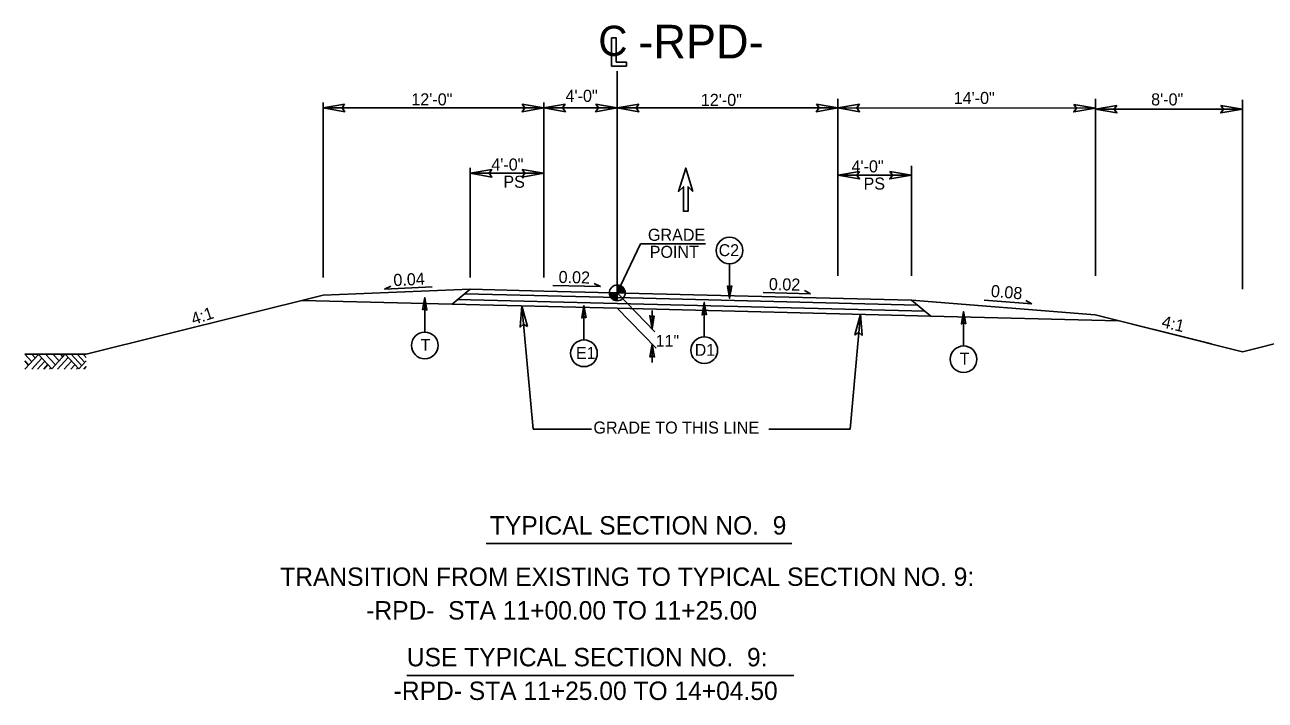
# Model space of a CAD drawing. Extents: x 1901582 to 1902252, y 193723 to 194156.
# Drawn here: x 1902017 to 1902084.4, y 193732 to 193768.8 of the extents above; entities that cross this region are included whole.
import ezdxf

# ---------------------------------------------------------------- set-up
doc = ezdxf.new("R2010")
doc.units = 0
for name, color, linetype in [('Old_Level_1', 7, 'Continuous'), ('Old_Level_11', 7, 'Continuous'), ('Old_Level_2', 7, 'Continuous'), ('Old_Level_20', 7, 'Continuous'), ('Prop Dimension', 7, 'Continuous'), ('Prop Dimension Text', 7, 'Continuous'), ('Typical Grade Point Symbol CELL', 7, 'Continuous'), ('Typical Pavement Slope Information CELL', 7, 'Continuous'), ('Typical Slope Point Local CELL', 7, 'Continuous'), ('Typical Terminator CELL', 7, 'Continuous'), ('Typical Text Centerline CELL', 7, 'Continuous'), ('Typical Text General CELL', 7, 'Continuous'), ('Typical Text Grade Point CELL', 7, 'Continuous')]:
    doc.layers.add(name, color=color, linetype=linetype)

# ---------------------------------------------------------------- blocks, each defined once
blk = doc.blocks.new('TERMINATOR')
at = {"layer": 'Typical Terminator CELL'}
blk.add_lwpolyline([(-0.469, 0.081), (0, 0), (-0.471, -0.083), (-0.411, 0)], close=True, dxfattribs=at)

msp = doc.modelspace()

# ---------------------------------------------------------------- linework, layer by layer
at = {"layer": 'Old_Level_1'}
for p, q in [((1902083.192, 193754.369), (1902083.192, 193764.667)), ((1902075.193, 193764.167), (1902083.193, 193764.167)), ((1902041.192, 193754.359), (1902033.192, 193754.039)), ((1902041.196, 193754.359), (1902040.203, 193753.551)), ((1902040.899, 193754.117), (1902049.192, 193753.909)), ((1902041.192, 193754.359), (1902045.193, 193754.259)), ((1902045.193, 193754.259), (1902065.192, 193753.759)), ((1902049.192, 193754.159), (1902051.241, 193752.043)), ((1902033.192, 193754.039), (1902020.31, 193750.819)), ((1902032.052, 193753.754), (1902040.203, 193753.551)), ((1902040.203, 193753.551), (1902049.192, 193753.326)), ((1902040.501, 193753.793), (1902049.192, 193753.576)), ((1902044.001, 193753.456), (1902044.618, 193746.746)), ((1902049.192, 193753.909), (1902065.511, 193753.501)), ((1902049.192, 193753.576), (1902065.933, 193753.157)), ((1902065.194, 193753.759), (1902075.192, 193752.959)), ((1902065.194, 193753.759), (1902066.25, 193752.899)), ((1902049.192, 193753.326), (1902066.25, 193752.899)), ((1902049.192, 193753.326), (1902051.299, 193751.15)), ((1902051.084, 193753.206), (1902051.084, 193752.206)), ((1902062.424, 193752.995), (1902061.85, 193746.746)), ((1902066.25, 193752.899), (1902076.453, 193752.644)), ((1902075.192, 193752.959), (1902081.514, 193751.379)), ((1902051.084, 193751.372), (1902051.084, 193750.372)), ((1902047.786, 193746.746), (1902044.618, 193746.746)), ((1902061.85, 193746.746), (1902057.427, 193746.746))]:
    msp.add_line(p, q, dxfattribs=at)
for points in [[(1902075.192, 193752.959), (1902083.192, 193750.959)], [(1902091.192, 193752.959), (1902083.192, 193750.959)], [(1902016.968, 193750.819), (1902020.31, 193750.819)]]:
    msp.add_lwpolyline(points, dxfattribs=at)
at = {"layer": 'Old_Level_11'}
for p, q in [((1902049.192, 193754.159), (1902049.193, 193766.232)), ((1902055.296, 193755.742), (1902055.296, 193753.868)), ((1902038.722, 193752.027), (1902038.722, 193753.902)), ((1902047.381, 193751.598), (1902047.381, 193753.473)), ((1902053.924, 193751.764), (1902053.924, 193753.638)), ((1902068.027, 193751.273), (1902068.027, 193753.147)), ((1902016.968, 193750.819), (1902017.343, 193750.416)), ((1902016.968, 193750.014), (1902017.71, 193750.811)), ((1902017.343, 193750.819), (1902017.53, 193750.618)), ((1902017.71, 193750.811), (1902018.434, 193750.032)), ((1902018.101, 193750.819), (1902018.634, 193750.246)), ((1902018.434, 193750.032), (1902019.165, 193750.818)), ((1902018.499, 193750.819), (1902018.832, 193750.46)), ((1902018.901, 193750.819), (1902019.034, 193750.676)), ((1902019.165, 193750.818), (1902019.906, 193750.022)), ((1902019.487, 193750.819), (1902020.067, 193750.196)), ((1902019.82, 193750.819), (1902020.234, 193750.375)), ((1902020.14, 193750.819), (1902020.31, 193750.636)), ((1902016.968, 193750.457), (1902017.174, 193750.235)), ((1902017.342, 193750.014), (1902017.896, 193750.61)), ((1902017.651, 193750.014), (1902018.052, 193750.443)), ((1902017.998, 193750.014), (1902018.225, 193750.257)), ((1902018.309, 193750.014), (1902018.38, 193750.09)), ((1902018.744, 193750.014), (1902019.33, 193750.642)), ((1902019.114, 193750.014), (1902019.514, 193750.443)), ((1902019.48, 193750.014), (1902019.697, 193750.247)), ((1902019.775, 193750.014), (1902019.844, 193750.088)), ((1902019.906, 193750.022), (1902020.31, 193750.457)), ((1902020.176, 193750.014), (1902020.31, 193750.157)), ((1902042.053, 193740.514), (1902058.679, 193740.514)), ((1902037.745, 193733.341), (1902058.8, 193733.341))]:
    msp.add_line(p, q, dxfattribs=at)
for points in [[(1902055.181, 193754.54), (1902055.296, 193753.868), (1902055.416, 193754.543), (1902055.296, 193754.458)], [(1902038.606, 193753.23), (1902038.722, 193753.902), (1902038.841, 193753.226), (1902038.722, 193753.312)], [(1902047.496, 193752.801), (1902047.381, 193753.473), (1902047.261, 193752.797), (1902047.381, 193752.883)], [(1902054.04, 193752.966), (1902053.924, 193753.638), (1902053.805, 193752.963), (1902053.924, 193753.048)], [(1902068.142, 193752.475), (1902068.027, 193753.147), (1902067.907, 193752.472), (1902068.027, 193752.557)]]:
    msp.add_lwpolyline(points, close=True, dxfattribs=at)
for centre in [(1902055.296, 193756.468), (1902038.722, 193751.302), (1902047.381, 193750.873), (1902053.924, 193751.039), (1902068.027, 193750.547)]:
    msp.add_circle(centre, 0.725, dxfattribs=at)
at = {"layer": 'Prop Dimension'}
for p, q in [((1902033.192, 193754.995), (1902033.192, 193764.532)), ((1902045.193, 193764.232), (1902033.193, 193764.232)), ((1902045.192, 193754.995), (1902045.192, 193764.532)), ((1902049.193, 193764.232), (1902045.193, 193764.232)), ((1902061.193, 193764.232), (1902049.193, 193764.232)), ((1902061.193, 193755.094), (1902061.193, 193764.732)), ((1902061.193, 193764.232), (1902075.193, 193764.217)), ((1902075.193, 193755.094), (1902075.193, 193764.717)), ((1902041.192, 193754.995), (1902041.192, 193760.969)), ((1902065.193, 193755.094), (1902065.193, 193761.069)), ((1902045.192, 193760.669), (1902041.192, 193760.669)), ((1902061.193, 193760.569), (1902065.193, 193760.569))]:
    msp.add_line(p, q, dxfattribs=at)
msp.add_lwpolyline([(1902053.31, 193759.687), (1902053.039, 193759.937), (1902053.039, 193758.603), (1902052.789, 193758.603), (1902052.789, 193759.937), (1902052.518, 193759.687), (1902052.914, 193760.958)], close=True, dxfattribs=at)
msp.add_lwpolyline([(1902053.31, 193759.687), (1902053.039, 193759.937), (1902053.039, 193758.603), (1902052.789, 193758.603), (1902052.789, 193759.937), (1902052.518, 193759.687), (1902052.914, 193760.958)], close=True, dxfattribs=at)
at = {"layer": 'Typical Grade Point Symbol CELL'}
for p, q in [((1902048.763, 193754.159), (1902049.192, 193754.159)), ((1902049.192, 193753.73), (1902049.192, 193754.159)), ((1902049.192, 193754.159), (1902049.192, 193753.73)), ((1902049.192, 193754.159), (1902049.192, 193754.589)), ((1902049.622, 193754.159), (1902049.192, 193754.159))]:
    msp.add_line(p, q, dxfattribs=at)
for points in [[(1902048.765, 193754.159), (1902048.765, 193754.113)], [(1902048.773, 193754.159), (1902048.773, 193754.062)], [(1902048.782, 193754.159), (1902048.782, 193754.031)], [(1902048.791, 193754.159), (1902048.791, 193754.006)], [(1902048.799, 193754.159), (1902048.799, 193753.986)], [(1902048.808, 193754.159), (1902048.808, 193753.967)], [(1902048.816, 193754.159), (1902048.816, 193753.951)], [(1902048.825, 193754.159), (1902048.825, 193753.936)], [(1902048.834, 193754.159), (1902048.834, 193753.923)], [(1902048.842, 193754.159), (1902048.842, 193753.91)], [(1902048.851, 193754.159), (1902048.851, 193753.899)], [(1902048.859, 193754.159), (1902048.859, 193753.888)], [(1902048.868, 193754.159), (1902048.868, 193753.878)], [(1902048.876, 193754.159), (1902048.876, 193753.868)], [(1902048.885, 193754.159), (1902048.885, 193753.859)], [(1902048.894, 193754.159), (1902048.894, 193753.85)], [(1902048.902, 193754.159), (1902048.902, 193753.842)], [(1902048.911, 193754.159), (1902048.911, 193753.835)], [(1902048.919, 193754.159), (1902048.919, 193753.827)], [(1902048.928, 193754.159), (1902048.928, 193753.82)], [(1902048.937, 193754.159), (1902048.937, 193753.814)], [(1902048.945, 193754.159), (1902048.945, 193753.808)], [(1902048.954, 193754.159), (1902048.954, 193753.802)], [(1902048.962, 193754.159), (1902048.962, 193753.797)], [(1902048.971, 193754.159), (1902048.971, 193753.791)], [(1902048.98, 193754.159), (1902048.98, 193753.786)], [(1902048.988, 193754.159), (1902048.988, 193753.781)], [(1902048.997, 193754.159), (1902048.997, 193753.776)], [(1902049.005, 193754.159), (1902049.005, 193753.773)], [(1902049.014, 193754.159), (1902049.014, 193753.769)], [(1902049.023, 193754.159), (1902049.023, 193753.765)], [(1902049.031, 193754.159), (1902049.031, 193753.761)], [(1902049.04, 193754.159), (1902049.04, 193753.757)], [(1902049.048, 193754.159), (1902049.048, 193753.755)], [(1902049.057, 193754.159), (1902049.057, 193753.752)], [(1902049.066, 193754.159), (1902049.066, 193753.749)], [(1902049.074, 193754.159), (1902049.074, 193753.747)], [(1902049.083, 193754.159), (1902049.083, 193753.744)], [(1902049.091, 193754.159), (1902049.091, 193753.742)], [(1902049.1, 193754.159), (1902049.1, 193753.74)], [(1902049.109, 193754.159), (1902049.109, 193753.738)], [(1902049.117, 193754.159), (1902049.117, 193753.736)], [(1902049.126, 193754.159), (1902049.126, 193753.735)], [(1902049.134, 193754.159), (1902049.134, 193753.734)], [(1902049.143, 193754.159), (1902049.143, 193753.733)], [(1902049.151, 193754.159), (1902049.151, 193753.732)], [(1902049.16, 193754.159), (1902049.16, 193753.731)], [(1902049.169, 193754.159), (1902049.169, 193753.731)], [(1902049.177, 193754.159), (1902049.177, 193753.73)], [(1902049.186, 193754.159), (1902049.186, 193753.73), (1902049.186, 193753.73)], [(1902049.196, 193754.589), (1902049.196, 193754.589), (1902049.196, 193754.159)], [(1902049.205, 193754.589), (1902049.205, 193754.159)], [(1902049.214, 193754.588), (1902049.214, 193754.159)], [(1902049.222, 193754.588), (1902049.222, 193754.159)], [(1902049.231, 193754.587), (1902049.231, 193754.159)], [(1902049.239, 193754.586), (1902049.239, 193754.159)], [(1902049.248, 193754.585), (1902049.248, 193754.159)], [(1902049.256, 193754.584), (1902049.256, 193754.159)], [(1902049.265, 193754.583), (1902049.265, 193754.159)], [(1902049.274, 193754.581), (1902049.274, 193754.159)], [(1902049.282, 193754.58), (1902049.282, 193754.159)], [(1902049.291, 193754.578), (1902049.291, 193754.159)], [(1902049.299, 193754.576), (1902049.299, 193754.159)], [(1902049.308, 193754.573), (1902049.308, 193754.159)], [(1902049.317, 193754.571), (1902049.317, 193754.159)], [(1902049.325, 193754.568), (1902049.325, 193754.159)], [(1902049.334, 193754.565), (1902049.334, 193754.159)], [(1902049.342, 193754.562), (1902049.342, 193754.159)], [(1902049.351, 193754.559), (1902049.351, 193754.159)], [(1902049.36, 193754.555), (1902049.36, 193754.159)], [(1902049.368, 193754.551), (1902049.368, 193754.159)], [(1902049.377, 193754.547), (1902049.377, 193754.159)], [(1902049.385, 193754.543), (1902049.385, 193754.159)], [(1902049.394, 193754.538), (1902049.394, 193754.159)], [(1902049.403, 193754.534), (1902049.403, 193754.159)], [(1902049.411, 193754.529), (1902049.411, 193754.159)], [(1902049.42, 193754.524), (1902049.42, 193754.159)], [(1902049.428, 193754.518), (1902049.428, 193754.159)], [(1902049.437, 193754.513), (1902049.437, 193754.159)], [(1902049.446, 193754.506), (1902049.446, 193754.159)], [(1902049.454, 193754.5), (1902049.454, 193754.159)], [(1902049.463, 193754.494), (1902049.463, 193754.159)], [(1902049.471, 193754.486), (1902049.471, 193754.159)], [(1902049.48, 193754.478), (1902049.48, 193754.159)], [(1902049.489, 193754.471), (1902049.489, 193754.159)], [(1902049.497, 193754.462), (1902049.497, 193754.159)], [(1902049.506, 193754.453), (1902049.506, 193754.159)], [(1902049.514, 193754.444), (1902049.514, 193754.159)], [(1902049.523, 193754.433), (1902049.523, 193754.159)], [(1902049.531, 193754.423), (1902049.531, 193754.159)], [(1902049.54, 193754.411), (1902049.54, 193754.159)], [(1902049.549, 193754.399), (1902049.549, 193754.159)], [(1902049.557, 193754.386), (1902049.557, 193754.159)], [(1902049.566, 193754.371), (1902049.566, 193754.159)], [(1902049.574, 193754.356), (1902049.574, 193754.159)], [(1902049.583, 193754.338), (1902049.583, 193754.159)], [(1902049.592, 193754.318), (1902049.592, 193754.159)], [(1902049.6, 193754.294), (1902049.6, 193754.159)], [(1902049.609, 193754.264), (1902049.609, 193754.159)], [(1902049.617, 193754.221), (1902049.617, 193754.159)]]:
    msp.add_lwpolyline(points, dxfattribs=at)
msp.add_circle((1902049.192, 193754.16), 0.43, dxfattribs=at)
for start, end in [(179.99048, 269.99048), (359.99048, 89.99048)]:
    msp.add_arc((1902049.192, 193754.16), 0.43, start, end, dxfattribs=at)
at = {"layer": 'Typical Pavement Slope Information CELL'}
for p, q in [((1902036.54, 193754.356), (1902036.868, 193754.532)), ((1902039.125, 193754.485), (1902036.54, 193754.356)), ((1902045.685, 193754.569), (1902048.272, 193754.506)), ((1902048.272, 193754.506), (1902047.94, 193754.674)), ((1902057.12, 193754.181), (1902059.708, 193754.118)), ((1902059.708, 193754.118), (1902059.375, 193754.286)), ((1902069.151, 193753.763), (1902071.731, 193753.558)), ((1902071.731, 193753.558), (1902071.409, 193753.744))]:
    msp.add_line(p, q, dxfattribs=at)
at = {"layer": 'Typical Terminator CELL'}
for points in [[(1902034.364, 193764.434), (1902033.193, 193764.232), (1902034.371, 193764.024), (1902034.221, 193764.232)], [(1902044.021, 193764.434), (1902045.193, 193764.232), (1902044.015, 193764.024), (1902044.164, 193764.232)], [(1902046.364, 193764.434), (1902045.193, 193764.232), (1902046.371, 193764.024), (1902046.221, 193764.232)], [(1902048.021, 193764.434), (1902049.193, 193764.232), (1902048.015, 193764.024), (1902048.164, 193764.232)], [(1902050.364, 193764.434), (1902049.193, 193764.232), (1902050.371, 193764.024), (1902050.221, 193764.232)], [(1902060.021, 193764.434), (1902061.193, 193764.232), (1902060.015, 193764.024), (1902060.164, 193764.232)], [(1902062.364, 193764.434), (1902061.193, 193764.232), (1902062.371, 193764.024), (1902062.221, 193764.232)], [(1902074.021, 193764.419), (1902075.193, 193764.217), (1902074.015, 193764.009), (1902074.164, 193764.217)], [(1902076.364, 193764.369), (1902075.193, 193764.167), (1902076.371, 193763.959), (1902076.221, 193764.167)], [(1902082.021, 193764.369), (1902083.193, 193764.167), (1902082.015, 193763.959), (1902082.164, 193764.167)], [(1902042.364, 193760.87), (1902041.192, 193760.669), (1902042.37, 193760.46), (1902042.221, 193760.669)], [(1902044.021, 193760.87), (1902045.192, 193760.669), (1902044.014, 193760.46), (1902044.164, 193760.669)], [(1902062.364, 193760.77), (1902061.193, 193760.569), (1902062.371, 193760.36), (1902062.221, 193760.569)], [(1902064.021, 193760.77), (1902065.193, 193760.569), (1902064.014, 193760.36), (1902064.164, 193760.569)], [(1902044.301, 193752.339), (1902044.001, 193753.456), (1902043.904, 193752.296), (1902044.093, 193752.459)], [(1902062.515, 193751.842), (1902062.424, 193752.995), (1902062.117, 193751.872), (1902062.332, 193751.999)]]:
    msp.add_lwpolyline(points, close=True, dxfattribs=at)
at = {"layer": 'Typical Text Centerline CELL'}
msp.add_lwpolyline([(1902048.885, 193766.727), (1902048.884, 193766.503), (1902049.693, 193766.502), (1902049.693, 193766.726), (1902049.133, 193766.727), (1902049.135, 193768.04), (1902048.886, 193768.04)], close=True, dxfattribs=at)
at = {"layer": 'Typical Text Grade Point CELL'}
for p in [(1902049.192, 193754.159), (1902053.993, 193756.829)]:
    msp.add_line(p, (1902050.455, 193756.829), dxfattribs=at)

# ---------------------------------------------------------------- block references
at = {"layer": 'Old_Level_1', "xscale": 1.5, "yscale": 1.5}
for p, rotation in [((1902051.084, 193752.206), -90), ((1902051.084, 193751.372), 90)]:
    msp.add_blockref('TERMINATOR', p, dxfattribs=dict(at, rotation=rotation))

# ---------------------------------------------------------------- texts
at = {"layer": 'Old_Level_1'}
for s, p in [('8\'-0"', (1902078.227, 193764.365)), ('4\'-0"', (1902042.341, 193760.821)), ('4\'-0"', (1902061.931, 193760.721))]:
    msp.add_text(s, height=0.656, dxfattribs=at).set_placement(p)
at = {"layer": 'Old_Level_11'}
for s, p in [('TYPICAL SECTION NO.  9', (1902042.264, 193741.008)), ('TRANSITION FROM EXISTING TO TYPICAL SECTION NO. 9: ', (1902030.861, 193738.213)), ('-RPD-  STA 11+00.00 TO 11+25.00', (1902035.537, 193736.382)), ('USE TYPICAL SECTION NO.  9:', (1902037.745, 193733.835)), ('-RPD- STA 11+25.00 TO 14+04.50', (1902037.029, 193732.004))]:
    msp.add_text(s, height=1, dxfattribs=at).set_placement(p)
at = {"layer": 'Old_Level_2'}
for s, rotation, p in [('0.04', 2.64907, (1902037.03, 193754.529)), ('0.02', 358.80842, (1902045.996, 193754.703)), ('0.02', 358.80842, (1902057.431, 193754.316))]:
    msp.add_text(s, height=0.656, rotation=rotation, dxfattribs=at).set_placement(p)
at = {"layer": 'Old_Level_20'}
for s, height, p in [('C2', 0.6491, (1902054.707, 193756.161)), ('T', 0.649, (1902038.494, 193751.009)), ('11"', 0.6491, (1902051.283, 193751.227)), ('D1', 0.6491, (1902053.403, 193750.735)), ('E1', 0.6491, (1902046.947, 193750.57)), ('T', 0.649, (1902067.816, 193750.254))]:
    msp.add_text(s, height=height, dxfattribs=at).set_placement(p)
at = {"layer": 'Prop Dimension Text'}
for s, p in [('12\'-0"', (1902037.991, 193764.367)), ('4\'-0"', (1902046.379, 193764.559)), ('12\'-0"', (1902053.736, 193764.339)), ('14\'-0"', (1902067.488, 193764.443)), ('PS', (1902042.996, 193759.883)), ('PS', (1902062.586, 193759.783))]:
    msp.add_text(s, height=0.656, dxfattribs=at).set_placement(p)
at = {"layer": 'Typical Pavement Slope Information CELL'}
msp.add_text('0.08', height=0.656, rotation=355.19472, dxfattribs=at).set_placement((1902069.491, 193753.948))
at = {"layer": 'Typical Slope Point Local CELL'}
for rotation, p in [(18.90137, (1902026.146, 193752.406)), (346.9803, (1902078.76, 193752.293))]:
    msp.add_text('4:1', height=0.656, rotation=rotation, dxfattribs=at).set_placement(p)
at = {"layer": 'Typical Text Centerline CELL'}
msp.add_text('C', height=1.64, dxfattribs=at).set_placement((1902048.162, 193767.063))
msp.add_text('-RPD-', height=1.8323, rotation=0.00002, dxfattribs=at).set_placement((1902050.341, 193766.922))
at = {"layer": 'Typical Text General CELL'}
msp.add_text('GRADE TO THIS LINE', height=0.656, dxfattribs=at).set_placement((1902047.894, 193746.503))
at = {"layer": 'Typical Text Grade Point CELL'}
for s, p in [('GRADE', (1902050.858, 193756.995)), ('POINT', (1902050.954, 193756.067))]:
    msp.add_text(s, height=0.656, rotation=0, dxfattribs=at).set_placement(p)

doc.saveas('drawing.dxf')
